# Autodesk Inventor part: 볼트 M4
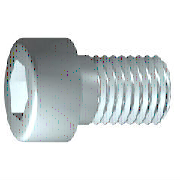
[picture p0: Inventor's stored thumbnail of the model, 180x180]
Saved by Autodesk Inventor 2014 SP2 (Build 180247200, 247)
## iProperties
IsCustomPart: 0
Created: 2018-09
Part Number: 볼트 M4
Material: 스테인리스강
Description: 6각머리 태핑 나사
Document SubType Name: Modeling
Standard: KS B 1003
Standards Organization: KS
Language: ko-KR
Size Designation: M 4 x 10
Categories: <MemberInstance><Categories><Category DisplayName="조임쇠" InternalName="e4da775c-781d-43d5-af7c-5136215cf5a6" Mnemonic="FSTN"><Category DisplayName="볼트" InternalN
Density: 1 g/cm^3
Appearance: 반광택
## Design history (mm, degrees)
sketch "스케치1"
  geometry: L1 (-1, 0)-(10, 0); L2 (10, 0)-(10, 2); L3 (10, 2)-(1.75, 2); L4 (1.75, 2)-(1.32, 2); L5 (1.32, 2)-(0, 2); L6 (0, 2)-(0, 3.5); L7 (0, 3.5)-(-4, 3.5); L8 (-4, 3.5)-(-4, 1.732); L9 (-4, 1.732)-(-2, 1.732); L10 (-2, 1.732)-(-1, 0); L11 (-6.8, 0)-(12.8, 0) reference; L12 (0, -0.7)-(0, 4.2) reference; L13 (1.75, 2)-(0, 2)
  constraints: 22 end point, 6 parallel, 2 collinear, 2 perpendicular, 1 horizontal, 1 point on line
  dimensions: "d1" = 8.25 distance from line of L3.end L2 (= GEL); "d2" = 0.42952 distance of L4.end L3.end (computed from GAL); "d3" = 4 distance between parallel lines of L8 L6 (= KOH); "d4" = 2 distance of L8.end L9.end (= INTI); "d5" = 60 deg angle of L10 L1; "d6" = 4 diameter of L3 L1 (= GD); "d7" = 4 diameter of L5 L1 (= BDM); "d8" = 3.4641 diameter of L9 L1 (= 1.1547 x SW); "d9" = 7 diameter of L7 L1 (= KOD); "d26" = 10 distance between parallel lines of L12 L2 (= NLG)
revolve "본체" sketch "스케치1" stored, may be unused: angle "d10" = 90 deg
sketch "스케치2"
  geometry: L1 (0, -4.9)-(0, 4.9) reference; L2 (-4.9, 0)-(4.9, 0) reference; L3 (1.732, 0)-(0.866, -1.5); L4 (0.866, -1.5)-(-0.866, -1.5); L5 (-0.866, -1.5)-(-1.732, 0); L6 (-1.732, 0)-(-0.866, 1.5); L7 (-0.866, 1.5)-(0.866, 1.5); L8 (0.866, 1.5)-(1.732, 0); 2 further points
  constraints: 12 end point, 1 coincident, 1 horizontal alignment, 1 point on line, 12 other
extrude "슬롯" join sketch "스케치2" stored distance "d11" = 10; taper "d12" = 0 deg
workplane "Work Plane1"
fillet "Fillet2" dims "d30" = 0.1 (= R)
body "Solid1"
fillet "모깎기1" dims "d17" = 0.4 (= RR)
feature "스레드" dims "d13" = 8.25 (= GEL), "d14" = 0
chamfer "모따기1" distance "d15" = 0.42941 (= -0.5 x SPD + 0.5 x GD); stored, may be unused: second distance "d16" = 0.42941 (= GUL), angle "d27" = 45 deg
other parameters: "GD" = 4 (= NND) [user parameter; used in 2 equation terms], "NLG" = 10 [user parameter; used in 1 equation term], "GEL" = 8.25 [user parameter; used in 2 equation terms], "KOD" = 7 [user parameter; used in 1 equation term], "KOH" = 4 [user parameter; used in 1 equation term], "INTI" = 2 [user parameter; used in 1 equation term], "GAL" = 0.42941 (= 0.61345 x PTC) [user parameter; used in 1 equation term], "GUL" = 0.42941 (= 0.61345 x PTC) [user parameter; used in 1 equation term], "BDM" = 4 (= NND) [user parameter; used in 1 equation term], "SW" = 3 [user parameter; used in 2 equation terms], "RR" = 0.4 [user parameter; used in 1 equation term], "SPD" = 3.14117 (= NND - 1.2269 x PTC) [user parameter; used in 1 equation term], "d19" = 0, "d28" = 0, "d29" = 0, "R" = 0.1 [user parameter; used in 1 equation term], "PHH" = 0.2 [user parameter], "GD1" = 3.14117 (= THREADDIA - 1.2269 x PTC) [user parameter], "THREADDIA" = 4 [user parameter; used in 1 equation term], "FAWI" = 45 deg [user parameter], "TPU" = 14.28571 (computed from PTC) [user parameter], "PTC" = 0.7 [user parameter; used in 5 equation terms], "NND" = 4 [user parameter; used in 3 equation terms], "TOA" = 30 deg [user parameter], "E0" = 3.465 (= 1.155 x SW) [user parameter]
